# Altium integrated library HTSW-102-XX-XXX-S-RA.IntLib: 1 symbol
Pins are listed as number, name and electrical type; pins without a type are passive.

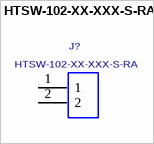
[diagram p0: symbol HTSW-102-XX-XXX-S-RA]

## HTSW-102-XX-XXX-S-RA
designator J?
.025 SQ POST HI-TEMP SINGLE ROW TERMINAL STRIP ASSEMBLY, 2 PINS.; MANUFACTURER: SAMTEC
footprint HTSW-102-XX-XXX-S-RA
pins: 1, 2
